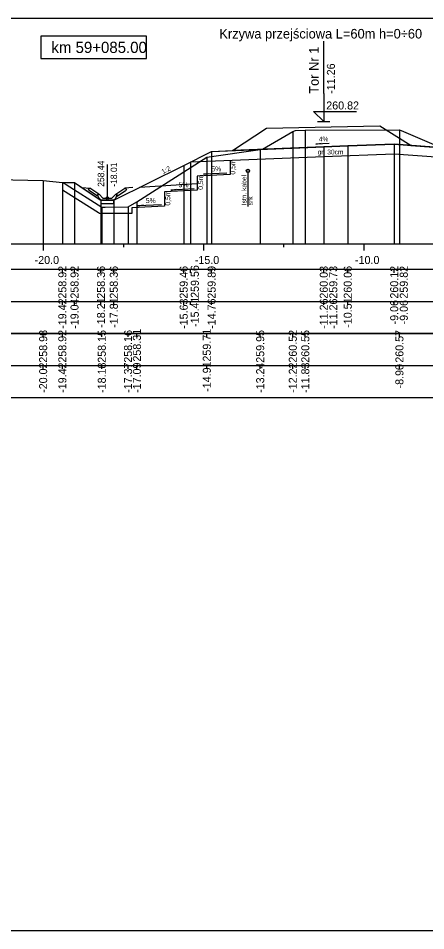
# Model space of a CAD drawing. Extents: x 6516023 to 6560129, y 5513077 to 5529206.
# Drawn here: x 6517289.42 to 6517302.14, y 5514518.16 to 5514546.66 of the extents above; entities that cross this region are included whole.
import ezdxf

# ---------------------------------------------------------------- set-up
doc = ezdxf.new("R2010")
doc.units = 0
for name, color, linetype in [('IR_default', 7, 'Continuous'), ('TOR_PRZEK_P-kable', 7, 'Continuous'), ('TOR_PRZEK_P-komponent', 7, 'Continuous'), ('TOR_PRZEK_P-odwodnienie', 7, 'Continuous'), ('TOR_PRZEK_P-opisy', 7, 'Continuous'), ('TOR_PRZEK_P-schodkowanie+wymiana', 7, 'Continuous'), ('TOR_PRZEK_P-tabelka istniejace', 7, 'Continuous'), ('TOR_PRZEK_P-tabelka projektowane', 7, 'Continuous'), ('TOR_PRZEK_P-teren istniejacy', 7, 'Continuous'), ('TOR_PRZEK_P-tory projektowane', 7, 'Continuous'), ('TOR_PRZEK_P-uklad odniesienia', 7, 'Continuous'), ('TOR_PRZEK_P-warstwa ochronna I', 7, 'Continuous'), ('TOR_PRZEK_P-warstwa ochronna II', 7, 'Continuous'), ('TOR_PS_T-skarpy projektowane', 7, 'Continuous'), ('TOR_RAMKI-ramka+tabelka 1', 7, 'Continuous')]:
    doc.layers.add(name, color=color, linetype=linetype)

msp = doc.modelspace()

# ---------------------------------------------------------------- linework, layer by layer
at = {"layer": 'IR_default'}
msp.add_lwpolyline([(6517290.797, 5514541.526), (6517291.177, 5514541.522), (6517291.508, 5514541.301), (6517292.003, 5514540.971), (6517292.403, 5514540.971), (6517294.584, 5514542.062), (6517294.585, 5514542.062), (6517295.454, 5514542.497), (6517296.113, 5514542.523), (6517297.168, 5514543.226), (6517300.704, 5514543.297)], dxfattribs=at)
at = {"layer": 'TOR_PRZEK_P-kable'}
msp.add_line((6517296.589, 5514541.889), (6517296.589, 5514540.779), dxfattribs=at)
msp.add_circle((6517296.589, 5514541.889), 0.05, dxfattribs=at)
at = {"layer": 'TOR_PRZEK_P-komponent'}
msp.add_lwpolyline([(6517297.168, 5514543.226), (6517300.704, 5514543.297), (6517301.685, 5514542.685), (6517303.076, 5514542.581), (6517303.963, 5514543.245), (6517307.463, 5514543.246), (6517308.463, 5514543.246), (6517311.963, 5514543.246), (6517312.513, 5514543.247), (6517316.013, 5514543.247), (6517317.359, 5514542.35), (6517313.513, 5514542.504), (6517310.213, 5514542.636), (6517309.463, 5514542.666), (6517308.263, 5514542.714), (6517307.663, 5514542.714), (6517306.463, 5514542.666), (6517305.713, 5514542.636), (6517303.513, 5514542.548), (6517301.154, 5514542.725), (6517299.704, 5514542.667), (6517298.954, 5514542.637), (6517296.113, 5514542.523)], close=True, dxfattribs=at)
at = {"layer": 'TOR_PRZEK_P-odwodnienie'}
for p, q in [((6517292.203, 5514541.041), (6517292.203, 5514542.085)), ((6517291.894, 5514541.1), (6517291.633, 5514541.275)), ((6517291.939, 5514541.167), (6517291.658, 5514541.354)), ((6517291.905, 5514541.117), (6517291.894, 5514541.1)), ((6517291.896, 5514541.136), (6517291.943, 5514541.16)), ((6517291.939, 5514541.167), (6517291.93, 5514541.154)), ((6517292.063, 5514541.041), (6517291.943, 5514541.16)), ((6517292.343, 5514541.041), (6517292.463, 5514541.16)), ((6517292.463, 5514541.16), (6517292.511, 5514541.136)), ((6517292.468, 5514541.167), (6517292.748, 5514541.354)), ((6517292.468, 5514541.167), (6517292.476, 5514541.154)), ((6517292.501, 5514541.117), (6517292.512, 5514541.1)), ((6517292.512, 5514541.1), (6517292.773, 5514541.275)), ((6517292.013, 5514540.971), (6517292.393, 5514540.971)), ((6517292.063, 5514541.041), (6517292.343, 5514541.041))]:
    msp.add_line(p, q, dxfattribs=at)
for points in [[(6517291.412, 5514541.366), (6517291.658, 5514541.354)], [(6517291.608, 5514541.327), (6517291.658, 5514541.354)], [(6517291.608, 5514541.327), (6517291.633, 5514541.275)], [(6517291.93, 5514541.154), (6517291.895, 5514541.136)], [(6517291.895, 5514541.136), (6517291.905, 5514541.117)], [(6517291.943, 5514541.041), (6517291.896, 5514541.136)], [(6517292.463, 5514541.041), (6517292.511, 5514541.136)], [(6517292.476, 5514541.154), (6517292.511, 5514541.136)], [(6517292.511, 5514541.136), (6517292.501, 5514541.117)], [(6517292.995, 5514541.366), (6517292.748, 5514541.354)], [(6517292.798, 5514541.327), (6517292.748, 5514541.354)], [(6517292.798, 5514541.327), (6517292.773, 5514541.275)], [(6517292.013, 5514540.971), (6517291.943, 5514541.041)], [(6517292.003, 5514540.971), (6517292.002, 5514540.972), (6517292.003, 5514540.971), (6517292.002, 5514540.971), (6517292.003, 5514540.971), (6517292.003, 5514540.971), (6517292.003, 5514540.971), (6517292.003, 5514540.972)], [(6517292.003, 5514540.971), (6517292.003, 5514540.972), (6517292.003, 5514540.971), (6517292.003, 5514540.971), (6517292.003, 5514540.971), (6517292.004, 5514540.971), (6517292.003, 5514540.971), (6517292.004, 5514540.972)], [(6517292.403, 5514540.971), (6517292.003, 5514540.971), (6517292.003, 5514540.871), (6517292.403, 5514540.871), (6517292.403, 5514540.971)], [(6517292.393, 5514540.971), (6517292.463, 5514541.041)], [(6517292.403, 5514540.971), (6517292.402, 5514540.972), (6517292.403, 5514540.971), (6517292.402, 5514540.971), (6517292.403, 5514540.971), (6517292.403, 5514540.971), (6517292.403, 5514540.971), (6517292.403, 5514540.972)], [(6517292.403, 5514540.971), (6517292.403, 5514540.972), (6517292.403, 5514540.971), (6517292.403, 5514540.971), (6517292.403, 5514540.971), (6517292.404, 5514540.971), (6517292.403, 5514540.971), (6517292.404, 5514540.972)]]:
    msp.add_lwpolyline(points, dxfattribs=at)
msp.add_circle((6517292.203, 5514541.041), 0.035, dxfattribs=at)
at = {"layer": 'TOR_PRZEK_P-opisy'}
msp.add_lwpolyline([(6517299.124, 5514542.742), (6517298.706, 5514542.723), (6517298.874, 5514542.751)], dxfattribs=at)
at = {"layer": 'TOR_PRZEK_P-schodkowanie+wymiana'}
for p, q in [((6517296.03, 5514542.22), (6517296.03, 5514541.777)), ((6517296.03, 5514541.777), (6517295.007, 5514541.726)), ((6517295.007, 5514541.726), (6517295.007, 5514541.283)), ((6517295.007, 5514541.482), (6517293.201, 5514541.375)), ((6517295.007, 5514541.283), (6517293.984, 5514541.231)), ((6517293.984, 5514541.231), (6517293.984, 5514540.788)), ((6517292.961, 5514540.558), (6517292.003, 5514540.555)), ((6517293.984, 5514540.788), (6517292.961, 5514540.737)), ((6517292.961, 5514540.737), (6517292.961, 5514540.558))]:
    msp.add_line(p, q, dxfattribs=at)
at = {"layer": 'TOR_PRZEK_P-tabelka istniejace'}
for p, q in [((6517290.198, 5514536.706), (6517290.198, 5514536.806)), ((6517290.797, 5514536.706), (6517290.797, 5514536.806)), ((6517292.029, 5514536.706), (6517292.029, 5514536.806)), ((6517292.847, 5514536.706), (6517292.847, 5514536.806)), ((6517293.124, 5514536.706), (6517293.124, 5514536.806)), ((6517295.306, 5514536.706), (6517295.306, 5514536.806)), ((6517296.972, 5514536.706), (6517296.972, 5514536.806)), ((6517297.99, 5514536.706), (6517297.99, 5514536.806)), ((6517298.38, 5514536.706), (6517298.38, 5514536.806)), ((6517301.318, 5514536.706), (6517301.318, 5514536.806)), ((6517269.163, 5514535.806), (6517352.963, 5514535.806)), ((6517290.198, 5514535.706), (6517290.198, 5514535.806)), ((6517290.797, 5514535.706), (6517290.797, 5514535.806)), ((6517292.029, 5514535.706), (6517292.029, 5514535.806)), ((6517292.847, 5514535.706), (6517292.847, 5514535.806)), ((6517293.124, 5514535.706), (6517293.124, 5514535.806)), ((6517295.306, 5514535.706), (6517295.306, 5514535.806)), ((6517296.972, 5514535.706), (6517296.972, 5514535.806)), ((6517297.99, 5514535.706), (6517297.99, 5514535.806)), ((6517298.38, 5514535.706), (6517298.38, 5514535.806)), ((6517301.318, 5514535.706), (6517301.318, 5514535.806))]:
    msp.add_line(p, q, dxfattribs=at)
for points in [[(6517297.99, 5514543.121), (6517297.99, 5514539.806), (6517297.99, 5514539.676), (6517297.99, 5514539.606)], [(6517298.38, 5514543.158), (6517298.38, 5514539.806), (6517298.38, 5514539.676), (6517298.38, 5514539.606)], [(6517301.318, 5514543.176), (6517301.318, 5514539.806), (6517301.318, 5514539.676), (6517301.318, 5514539.606)], [(6517296.972, 5514542.552), (6517296.972, 5514539.806), (6517296.972, 5514539.676), (6517296.972, 5514539.606)], [(6517295.306, 5514542.32), (6517295.306, 5514539.806), (6517295.306, 5514539.676), (6517295.306, 5514539.606)], [(6517290.198, 5514541.591), (6517290.198, 5514539.806), (6517290.198, 5514539.676), (6517290.198, 5514539.606)], [(6517290.797, 5514541.526), (6517290.797, 5514539.806), (6517290.797, 5514539.676), (6517290.797, 5514539.606)], [(6517293.124, 5514540.918), (6517293.124, 5514539.806), (6517293.124, 5514539.676), (6517293.124, 5514539.606)], [(6517292.029, 5514540.753), (6517292.029, 5514539.806), (6517292.029, 5514539.676), (6517292.029, 5514539.606)], [(6517292.847, 5514540.765), (6517292.847, 5514539.806), (6517292.847, 5514539.676), (6517292.847, 5514539.606)]]:
    msp.add_lwpolyline(points, dxfattribs=at)
msp.add_lwpolyline([(6517269.163, 5514536.806), (6517269.163, 5514534.806), (6517352.963, 5514534.806), (6517352.963, 5514536.806)], close=True, dxfattribs=at)
at = {"layer": 'TOR_PRZEK_P-tabelka projektowane'}
for p, q in [((6517290.797, 5514538.706), (6517290.797, 5514538.806)), ((6517291.177, 5514538.706), (6517291.177, 5514538.806)), ((6517292.003, 5514538.706), (6517292.003, 5514538.806)), ((6517292.403, 5514538.706), (6517292.403, 5514538.806)), ((6517294.584, 5514538.706), (6517294.584, 5514538.806)), ((6517294.802, 5514538.706), (6517294.802, 5514538.806)), ((6517295.456, 5514538.706), (6517295.456, 5514538.806)), ((6517298.954, 5514538.706), (6517298.954, 5514538.806)), ((6517298.956, 5514538.706), (6517298.956, 5514538.806)), ((6517299.705, 5514538.706), (6517299.705, 5514538.806)), ((6517301.154, 5514538.706), (6517301.154, 5514538.806)), ((6517301.155, 5514538.706), (6517301.155, 5514538.806)), ((6517269.163, 5514537.806), (6517352.963, 5514537.806)), ((6517290.797, 5514537.706), (6517290.797, 5514537.806)), ((6517291.177, 5514537.706), (6517291.177, 5514537.806)), ((6517292.003, 5514537.706), (6517292.003, 5514537.806)), ((6517292.403, 5514537.706), (6517292.403, 5514537.806)), ((6517294.584, 5514537.706), (6517294.584, 5514537.806)), ((6517294.802, 5514537.706), (6517294.802, 5514537.806)), ((6517295.456, 5514537.706), (6517295.456, 5514537.806)), ((6517298.954, 5514537.706), (6517298.954, 5514537.806)), ((6517298.956, 5514537.706), (6517298.956, 5514537.806)), ((6517299.705, 5514537.706), (6517299.705, 5514537.806)), ((6517301.154, 5514537.706), (6517301.154, 5514537.806)), ((6517301.155, 5514537.706), (6517301.155, 5514537.806))]:
    msp.add_line(p, q, dxfattribs=at)
for points in [[(6517298.956, 5514542.637), (6517298.956, 5514539.806), (6517298.956, 5514539.676), (6517298.956, 5514539.606)], [(6517299.705, 5514542.667), (6517299.705, 5514539.806), (6517299.705, 5514539.676), (6517299.705, 5514539.606)], [(6517301.155, 5514542.725), (6517301.155, 5514539.806), (6517301.155, 5514539.676), (6517301.155, 5514539.606)], [(6517295.456, 5514542.497), (6517295.456, 5514539.806), (6517295.456, 5514539.676), (6517295.456, 5514539.606)], [(6517298.954, 5514542.337), (6517298.954, 5514539.806), (6517298.954, 5514539.676), (6517298.954, 5514539.606)], [(6517301.154, 5514542.425), (6517301.154, 5514539.806), (6517301.154, 5514539.676), (6517301.154, 5514539.606)], [(6517294.584, 5514542.062), (6517294.584, 5514539.806), (6517294.584, 5514539.676), (6517294.584, 5514539.606)], [(6517294.802, 5514542.171), (6517294.802, 5514539.806), (6517294.802, 5514539.676), (6517294.802, 5514539.606)], [(6517290.797, 5514541.526), (6517290.797, 5514539.806), (6517290.797, 5514539.676), (6517290.797, 5514539.606)], [(6517291.177, 5514541.522), (6517291.177, 5514539.806), (6517291.177, 5514539.676), (6517291.177, 5514539.606)], [(6517292.003, 5514540.971), (6517292.003, 5514539.806), (6517292.003, 5514539.676), (6517292.003, 5514539.606)], [(6517292.403, 5514540.971), (6517292.403, 5514539.806), (6517292.403, 5514539.676), (6517292.403, 5514539.606)]]:
    msp.add_lwpolyline(points, dxfattribs=at)
msp.add_lwpolyline([(6517269.163, 5514538.806), (6517269.163, 5514536.806), (6517352.963, 5514536.806), (6517352.963, 5514538.806)], close=True, dxfattribs=at)
at = {"layer": 'TOR_PRZEK_P-teren istniejacy'}
msp.add_lwpolyline([(6517288.766, 5514541.62), (6517290.198, 5514541.591), (6517290.797, 5514541.526), (6517290.916, 5514541.461), (6517292.029, 5514540.753), (6517292.13, 5514540.76), (6517292.847, 5514540.765), (6517293.124, 5514540.918), (6517295.306, 5514542.32), (6517296.972, 5514542.552), (6517297.043, 5514542.572), (6517297.99, 5514543.121), (6517298.079, 5514543.148), (6517298.38, 5514543.158), (6517301.318, 5514543.176), (6517301.368, 5514543.155), (6517302.397, 5514542.713)], dxfattribs=at)
at = {"layer": 'TOR_PRZEK_P-tory projektowane'}
for p, q in [((6517298.954, 5514544.304), (6517298.954, 5514545.937)), ((6517298.954, 5514544.304), (6517298.954, 5514543.427)), ((6517298.954, 5514543.427), (6517298.635, 5514543.746)), ((6517298.635, 5514543.746), (6517299.98, 5514543.746)), ((6517298.763, 5514543.427), (6517299.146, 5514543.427))]:
    msp.add_line(p, q, dxfattribs=at)
at = {"layer": 'TOR_PRZEK_P-uklad odniesienia'}
for p, q in [((6517272.963, 5514539.606), (6517352.963, 5514539.606)), ((6517290.213, 5514539.406), (6517290.213, 5514539.606)), ((6517292.713, 5514539.506), (6517292.713, 5514539.606)), ((6517295.213, 5514539.406), (6517295.213, 5514539.606)), ((6517297.713, 5514539.506), (6517297.713, 5514539.606)), ((6517300.213, 5514539.406), (6517300.213, 5514539.606))]:
    msp.add_line(p, q, dxfattribs=at)
msp.add_lwpolyline([(6517293.428, 5514546.097), (6517290.128, 5514546.097), (6517290.128, 5514545.397), (6517293.428, 5514545.397)], close=True, dxfattribs=at)
at = {"layer": 'TOR_PRZEK_P-warstwa ochronna I'}
msp.add_lwpolyline([(6517294.802, 5514542.171), (6517298.954, 5514542.337), (6517301.154, 5514542.425), (6517303.332, 5514542.262)], dxfattribs=at)
at = {"layer": 'TOR_PRZEK_P-warstwa ochronna II'}
msp.add_lwpolyline([(6517290.797, 5514541.526), (6517291.177, 5514541.522), (6517292.003, 5514540.971), (6517292.403, 5514540.971), (6517294.584, 5514542.062), (6517294.585, 5514542.062), (6517295.456, 5514542.497), (6517298.956, 5514542.637), (6517299.705, 5514542.667), (6517301.155, 5514542.725), (6517303.513, 5514542.548), (6517305.714, 5514542.636), (6517306.464, 5514542.666), (6517307.664, 5514542.714), (6517308.264, 5514542.714), (6517309.463, 5514542.666), (6517310.214, 5514542.636), (6517313.513, 5514542.504), (6517314.263, 5514542.474), (6517318.564, 5514542.302), (6517319.433, 5514541.867)], dxfattribs=at)
at = {"layer": 'TOR_PS_T-skarpy projektowane'}
for points in [[(6517295.936, 5514541.821), (6517295.201, 5514541.782), (6517295.374, 5514541.812)], [(6517290.797, 5514541.299), (6517291.922, 5514540.584)], [(6517294.914, 5514541.327), (6517294.178, 5514541.287), (6517294.351, 5514541.318)], [(6517293.891, 5514540.833), (6517293.156, 5514540.793), (6517293.328, 5514540.824)]]:
    msp.add_lwpolyline(points, dxfattribs=at)
msp.add_arc((6517292.029, 5514540.753), 0.2, 237.558, 262.6684, dxfattribs=at)
at = {"layer": 'TOR_RAMKI-ramka+tabelka 1'}
msp.add_lwpolyline([(6517179.513, 5514546.656), (6517427.013, 5514546.656), (6517427.013, 5514518.156), (6517179.513, 5514518.156)], close=True, dxfattribs=at)

# ---------------------------------------------------------------- texts
at = {"layer": 'TOR_PRZEK_P-kable'}
for s, height, p in [('Istn. kabel', 0.14999, (6517296.544, 5514540.816)), ('srk', 0.15, (6517296.738, 5514540.816))]:
    msp.add_text(s, height=height, rotation=90.0511, dxfattribs=at).set_placement(p)
at = {"layer": 'TOR_PRZEK_P-odwodnienie'}
for s, p in [('258.44', (6517292.103, 5514541.391)), ('-18.01', (6517292.503, 5514541.391))]:
    msp.add_text(s, height=0.2, rotation=90, dxfattribs=at).set_placement(p)
at = {"layer": 'TOR_PRZEK_P-opisy'}
for s, rotation, p in [('4%', 0.1515, (6517298.801, 5514542.807)), ('1:2', 27.0701, (6517293.939, 5514541.786))]:
    msp.add_text(s, height=0.15, rotation=rotation, dxfattribs=at).set_placement(p)
at = {"layer": 'TOR_PRZEK_P-schodkowanie+wymiana'}
for p in [(6517296.196, 5514541.774), (6517295.189, 5514541.298), (6517294.166, 5514540.804)]:
    msp.add_text('0,5m', height=0.1545, rotation=90, dxfattribs=at).set_placement(p)
at = {"layer": 'TOR_PRZEK_P-tabelka istniejace'}
for s, p in [('258.98', (6517290.323, 5514535.898)), ('258.92', (6517290.922, 5514535.9)), ('258.15', (6517292.154, 5514535.897)), ('258.16', (6517292.972, 5514535.898)), ('258.31', (6517293.249, 5514535.933)), ('259.71', (6517295.431, 5514535.933)), ('259.95', (6517297.097, 5514535.897)), ('260.52', (6517298.115, 5514535.9)), ('260.55', (6517298.505, 5514535.897)), ('260.57', (6517301.443, 5514535.898)), ('-20.02', (6517290.323, 5514534.956)), ('-19.42', (6517290.922, 5514534.956)), ('-18.18', (6517292.154, 5514534.954)), ('-17.37', (6517292.972, 5514534.955)), ('-17.09', (6517293.249, 5514534.955)), ('-14.91', (6517295.431, 5514534.989)), ('-13.24', (6517297.097, 5514534.955)), ('-12.22', (6517298.115, 5514534.956)), ('-11.83', (6517298.505, 5514534.954)), ('-8.90', (6517301.443, 5514535.094))]:
    msp.add_text(s, height=0.25, rotation=90, dxfattribs=at).set_placement(p)
at = {"layer": 'TOR_PRZEK_P-tabelka projektowane'}
for s, p in [('258.92', (6517290.922, 5514537.9)), ('258.92', (6517291.302, 5514537.9)), ('258.36', (6517292.128, 5514537.898)), ('258.36', (6517292.528, 5514537.898)), ('259.46', (6517294.709, 5514537.898)), ('259.56', (6517295.057, 5514537.923)), ('259.89', (6517295.581, 5514537.898)), ('260.03', (6517299.081, 5514537.898)), ('259.73', (6517299.379, 5514537.898)), ('260.06', (6517299.83, 5514537.898)), ('260.12', (6517301.28, 5514537.9)), ('259.82', (6517301.579, 5514537.9)), ('-19.42', (6517290.922, 5514536.956)), ('-19.04', (6517291.302, 5514536.955)), ('-18.21', (6517292.128, 5514536.989)), ('-17.81', (6517292.528, 5514536.989)), ('-15.63', (6517294.709, 5514536.954)), ('-15.41', (6517295.057, 5514537.015)), ('-14.76', (6517295.581, 5514536.954)), ('-11.26', (6517299.081, 5514536.954)), ('-11.26', (6517299.379, 5514536.954)), ('-10.51', (6517299.83, 5514536.989)), ('-9.06', (6517301.28, 5514537.094)), ('-9.06', (6517301.579, 5514537.094))]:
    msp.add_text(s, height=0.25, rotation=90, dxfattribs=at).set_placement(p)
at = {"layer": 'TOR_PRZEK_P-tory projektowane'}
for s, height, rotation, p in [('Krzywa przejściowa L=60m h=0÷60', 0.3, 360, (6517295.697, 5514546.023)), ('Tor Nr 1', 0.3, 90, (6517298.8, 5514544.298)), ('-11.26', 0.25, 90, (6517299.304, 5514544.297))]:
    msp.add_text(s, height=height, rotation=rotation, dxfattribs=at).set_placement(p)
msp.add_text('260.82', height=0.25, dxfattribs=at).set_placement((6517299.034, 5514543.807))
at = {"layer": 'TOR_PRZEK_P-uklad odniesienia'}
for s, height, p in [('km 59+085.00', 0.35, (6517290.456, 5514545.572)), ('-20.0', 0.25, (6517289.932, 5514538.981)), ('-15.0', 0.25, (6517294.932, 5514538.981)), ('-10.0', 0.25, (6517299.932, 5514538.981))]:
    msp.add_text(s, height=height, dxfattribs=at).set_placement(p)
at = {"layer": 'TOR_PRZEK_P-warstwa ochronna I'}
msp.add_text('gr. 30cm', height=0.15, dxfattribs=at).set_placement((6517298.766, 5514542.403))
at = {"layer": 'TOR_PS_T-skarpy projektowane'}
for p in [(6517295.448, 5514541.873), (6517294.425, 5514541.379), (6517293.402, 5514540.884)]:
    msp.add_text('5%', height=0.1545, dxfattribs=at).set_placement(p)

doc.saveas('drawing.dxf')
